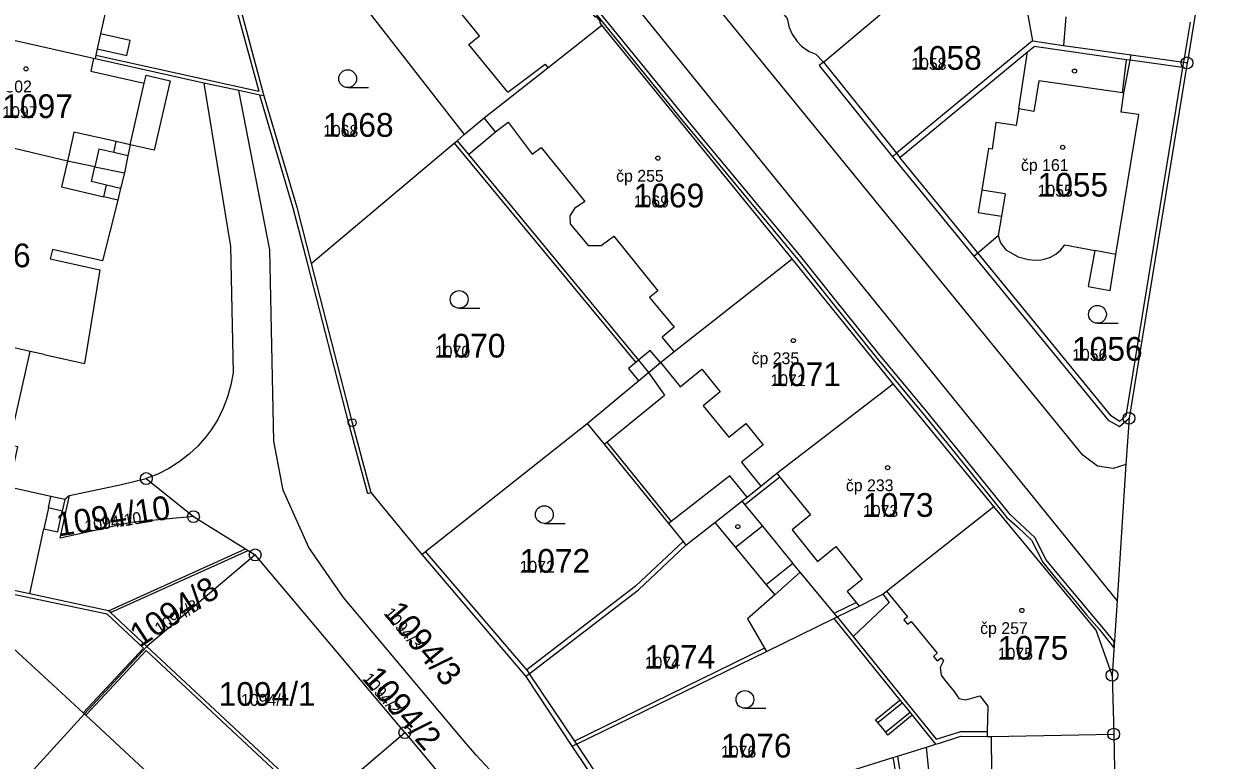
# Model space of a CAD drawing. Extents: x -763628 to -761565, y -976033 to -973833.
# Drawn here: x -761937.4 to -761836.8, y -975033.9 to -974971.8 of the extents above; entities that cross this region are included whole.
import ezdxf

# ---------------------------------------------------------------- set-up
doc = ezdxf.new("R2010")
doc.units = 0
for name, color, linetype in [('KN_cisla parcel 1000', 7, 'Continuous'), ('KN_cisla parcel 500', 7, 'Continuous'), ('KN_cisla popisna 500', 7, 'Continuous'), ('KN_hranice parcel', 7, 'Continuous'), ('KN_hranice uzemi', 7, 'Continuous'), ('KN_vecna bremena', 7, 'Continuous'), ('KN_vnitrni kresba parcel', 7, 'Continuous'), ('KN_znacky bodu BP', 7, 'Continuous'), ('KN_znacky budov', 7, 'Continuous'), ('KN_znacky kultur', 7, 'Continuous')]:
    doc.layers.add(name, color=color, linetype=linetype)

msp = doc.modelspace()

# ---------------------------------------------------------------- linework, layer by layer
at = {"layer": 'KN_hranice parcel'}
for p, q in [((-761919.62, -974968.69), (-761917.15, -974977.91)), ((-761931.5, -974974.74), (-761942.71, -974972.23)), ((-761872.6, -974991.65), (-761888.65, -974971.93)), ((-761919.25, -974977.45), (-761922.2, -974976.82)), ((-761913.16, -974992.03), (-761901.09, -974981.88)), ((-761864.16, -974983.03), (-761857.29, -974991.41)), ((-761864.1, -975002.17), (-761872.6, -974991.65)), ((-761889.88, -975005.51), (-761885.57, -975001.92)), ((-761855.6, -975012.52), (-761864.1, -975002.17)), ((-761927.06, -975010.16), (-761923.08, -975013.37)), ((-761923.08, -975013.37), (-761918.69, -975016.1)), ((-761881.56, -975015.78), (-761879.13, -975013.87)), ((-761930.24, -975021.3), (-761918.69, -975016.1)), ((-761917.88, -975016.6), (-761927.01, -975024.32)), ((-761905.26, -975031.58), (-761917.88, -975016.6)), ((-761903.82, -975016.56), (-761895.06, -975026.86)), ((-761874.78, -975024.73), (-761869.1, -975021.97)), ((-761912.56, -975037.76), (-761927.01, -975024.32)), ((-761895.06, -975026.86), (-761891.17, -975032.73)), ((-761912.56, -975037.76), (-761905.26, -975031.58)), ((-761891.17, -975032.73), (-761885.94, -975040.54))]:
    msp.add_line(p, q, dxfattribs=at)
for points in [[(-761888.65, -974971.93), (-761888.83, -974971.7), (-761888.76, -974971.64), (-761889.1, -974971.2), (-761889.19, -974971.27), (-761891.14, -974968.87), (-761891.06, -974968.8), (-761891.43, -974968.34), (-761891.52, -974968.41), (-761895.5, -974963.62), (-761895.48, -974963.45), (-761896.76, -974961.93), (-761896.92, -974961.89), (-761900.8, -974957.02), (-761900.71, -974956.95), (-761901.09, -974956.5), (-761901.17, -974956.57), (-761903.06, -974954.24), (-761902.95, -974954.15), (-761903.54, -974953.43), (-761903.65, -974953.52)], [(-761869.97, -974975.05), (-761862.24, -974968.54), (-761861.32, -974969.63), (-761857.11, -974965.94), (-761857.81, -974962.69), (-761865.17, -974953.41)], [(-761854.76, -974956.98), (-761853.89, -974963.11), (-761852.83, -974970.61), (-761852.36, -974973.26)], [(-761912.32, -974960.44), (-761909.57, -974964.01), (-761906.72, -974967.16), (-761909, -974969.94), (-761900.25, -974981.17)], [(-761879.04, -974964.81), (-761876.91, -974967.42), (-761876.54, -974967.14), (-761873.03, -974971.39), (-761872.86, -974972.14), (-761872.6, -974972.7), (-761872.19, -974973.32), (-761871.82, -974973.72), (-761871.17, -974974.16), (-761870.6, -974974.39), (-761869.97, -974975.05)], [(-761900.25, -974981.17), (-761898.57, -974979.76), (-761893.21, -974975.53), (-761888.65, -974971.93)], [(-761852.36, -974973.26), (-761863.81, -974982.74), (-761864.16, -974983.03)], [(-761852.36, -974973.26), (-761849.72, -974973.64), (-761844.04, -974974.45)], [(-761849.62, -974990.47), (-761847.1, -974990.94), (-761847.66, -974993.96), (-761845.81, -974994.32), (-761845.31, -974991.27), (-761843.39, -974979.48), (-761844.88, -974979.26), (-761844.64, -974977.66), (-761844.12, -974974.89), (-761844.04, -974974.45)], [(-761844.04, -974974.45), (-761839.62, -974975.07), (-761839.32, -974975.12)], [(-761931.5, -974974.74), (-761931.74, -974975.83), (-761927.23, -974976.84), (-761927.08, -974976.15), (-761925.06, -974976.63), (-761926.4, -974982.48), (-761928.41, -974982.03), (-761928.62, -974982.95), (-761929.8, -974982.68), (-761931.06, -974982.4), (-761931.39, -974983.88), (-761933.7, -974983.4), (-761944.59, -974980.81)], [(-761922.2, -974976.82), (-761931.38, -974974.77), (-761931.5, -974974.74)], [(-761869.97, -974975.05), (-761870.32, -974975.33), (-761864.16, -974983.03)], [(-761922.2, -974976.82), (-761919.95, -974990.59), (-761919.74, -975001.24)], [(-761883.72, -975050.21), (-761899.23, -975033.52), (-761900.44, -975032.09), (-761910.42, -975020.2), (-761913.35, -975015.98), (-761915.51, -975011.15), (-761916.32, -975007), (-761916.64, -974990.89), (-761919.25, -974977.45)], [(-761917.15, -974977.91), (-761917.49, -974977.83), (-761919.25, -974977.45)], [(-761917.15, -974977.91), (-761914.38, -974987.28), (-761913.16, -974992.03)], [(-761901.09, -974981.88), (-761900.86, -974981.69), (-761900.25, -974981.17)], [(-761901.09, -974981.88), (-761885.79, -975000.37), (-761886.42, -975000.89), (-761885.57, -975001.92)], [(-761857.29, -974991.41), (-761856.95, -974991.13), (-761855.23, -974989.67), (-761855.03, -974990.28), (-761854.6, -974990.88), (-761853.56, -974991.46), (-761852.69, -974991.69)], [(-761852.69, -974991.69), (-761852.16, -974991.76), (-761851.61, -974991.73), (-761851.35, -974991.68), (-761850.84, -974991.5), (-761850.37, -974991.24), (-761849.96, -974990.89), (-761849.62, -974990.47)], [(-761885.57, -975001.92), (-761884.71, -975001.21), (-761883.72, -975000.39), (-761882.56, -974999.46), (-761872.6, -974991.65)], [(-761857.29, -974991.41), (-761856.35, -974992.56), (-761845.98, -975005.25), (-761845, -975005.76), (-761844.21, -975005.08)], [(-761913.16, -974992.03), (-761909.7, -975005.45), (-761908.12, -975011.34), (-761903.82, -975016.56)], [(-761933.54, -975011.58), (-761933.93, -975011.93), (-761935.1, -975011.67), (-761938.63, -975010.89), (-761937.88, -975007.5), (-761938.61, -975007.34), (-761936.86, -974999.44), (-761948.14, -974996.86)], [(-761919.74, -975001.24), (-761919.92, -975002.27), (-761920.2, -975003.27), (-761920.58, -975004.24), (-761921.04, -975005.18), (-761921.6, -975006.06), (-761922.01, -975006.61), (-761922.69, -975007.4), (-761923.45, -975008.11), (-761924.28, -975008.75), (-761925.16, -975009.31), (-761926.09, -975009.78), (-761927.06, -975010.16)], [(-761879.13, -975013.87), (-761876.86, -975012.08), (-761876.41, -975011.73), (-761875.24, -975010.81), (-761873.89, -975009.72), (-761864.1, -975002.17)], [(-761903.82, -975016.56), (-761903.51, -975016.31), (-761889.88, -975005.51)], [(-761889.88, -975005.51), (-761888.45, -975007.27), (-761883.04, -975013.96), (-761881.81, -975015.47), (-761881.56, -975015.78)], [(-761933.54, -975011.58), (-761929.16, -975010.65), (-761927.06, -975010.16)], [(-761923.08, -975013.37), (-761928.37, -975013.86), (-761934.32, -975015.19), (-761933.54, -975011.58)], [(-761869.1, -975021.97), (-761868.82, -975021.83), (-761866.96, -975020.92), (-761865.46, -975020.17), (-761864.96, -975019.92), (-761864.66, -975019.66), (-761855.6, -975012.52)], [(-761845.64, -975026.74), (-761846.97, -975022.94), (-761855.6, -975012.52)], [(-761879.13, -975013.87), (-761877.38, -975015.98), (-761874.79, -975019.11), (-761874.08, -975019.96), (-761876.38, -975021.98), (-761874.93, -975024.47), (-761874.78, -975024.73)], [(-761895.06, -975026.86), (-761894.77, -975026.63), (-761885.57, -975019.55), (-761881.56, -975015.78)], [(-761930.24, -975021.3), (-761936.89, -975019.89), (-761940.12, -975019.2), (-761941.16, -975018.98), (-761952.58, -975016.42)], [(-761918.69, -975016.1), (-761918.48, -975016.23), (-761917.88, -975016.6)], [(-761927.01, -975024.32), (-761930.08, -975021.45), (-761930.24, -975021.3)], [(-761869.1, -975021.97), (-761863.52, -975028.84), (-761863.33, -975029.08), (-761862.67, -975029.89), (-761862.48, -975030.12), (-761860.51, -975032.56)], [(-761927.01, -975024.32), (-761932.26, -975030), (-761940.92, -975039.48)], [(-761891.17, -975032.73), (-761890.8, -975032.55), (-761874.78, -975024.73)], [(-761905.26, -975031.58), (-761902.96, -975034.31), (-761892.13, -975047.92)], [(-761860.51, -975032.56), (-761860.2, -975032.46), (-761858.38, -975031.89), (-761856.17, -975031.91), (-761855.84, -975031.91), (-761845.5, -975031.71)], [(-761864.11, -975033.69), (-761863.73, -975033.57), (-761861.29, -975032.8), (-761860.51, -975032.56)], [(-761885.94, -975040.54), (-761885.53, -975040.41), (-761864.11, -975033.69)], [(-761864.11, -975033.69), (-761864.05, -975034.09), (-761863.85, -975035.44), (-761862.06, -975047.4)]]:
    msp.add_lwpolyline(points, dxfattribs=at)
at = {"layer": 'KN_hranice uzemi'}
for p, q in [((-761839.32, -974975.12), (-761844.21, -975005.08)), ((-761845.64, -975026.74), (-761845.5, -975031.71)), ((-761845.5, -975031.71), (-761845.23, -975045.22))]:
    msp.add_line(p, q, dxfattribs=at)
for points in [[(-761836.78, -974959.74), (-761838.75, -974971.73), (-761839.29, -974975.03), (-761839.32, -974975.12)], [(-761844.21, -975005.08), (-761844.47, -975008.99), (-761845.22, -975020.43), (-761845.64, -975026.74)]]:
    msp.add_lwpolyline(points, dxfattribs=at)
at = {"layer": 'KN_vecna bremena'}
for points in [[(-761890.04, -974969.93), (-761881.82, -974980.04), (-761880.23, -974981.93), (-761872.16, -974991.67), (-761869.28, -974995.26), (-761865.58, -974999.87), (-761861.43, -975004.88), (-761858.76, -975008.16), (-761854.5, -975013.44), (-761853.62, -975014.24), (-761852.42, -975015.35), (-761851.48, -975017.2), (-761850.56, -975018.35), (-761848.93, -975020.27), (-761847.78, -975021.65), (-761846.72, -975022.87), (-761845.49, -975024.43), (-761845.45, -975023.91), (-761846.46, -975022.65), (-761847.52, -975021.43), (-761848.67, -975020.05), (-761850.28, -975018.13), (-761851.18, -975017), (-761852.14, -975015.13), (-761853.38, -975013.98)], [(-761853.38, -975013.98), (-761854.24, -975013.2), (-761858.48, -975007.94), (-761861.15, -975004.66), (-761865.3, -974999.65), (-761869, -974995.04), (-761871.88, -974991.45), (-761879.97, -974981.71), (-761881.54, -974979.82), (-761889.76, -974969.71)]]:
    msp.add_lwpolyline(points, dxfattribs=at)
at = {"layer": 'KN_vnitrni kresba parcel'}
for p, q in [((-761848.11, -975008.2), (-761927.52, -974910.73)), ((-761845.22, -975020.43), (-761927.29, -974919.04)), ((-761929.54, -974966.47), (-761930.92, -974972.68)), ((-761920.01, -974968.6), (-761917.58, -974977.51)), ((-761898.96, -974972.84), (-761901.31, -974969.96)), ((-761849.53, -974971.24), (-761849.72, -974973.64)), ((-761839.04, -974971.68), (-761839.62, -974975.07)), ((-761930.92, -974972.68), (-761931.2, -974973.94)), ((-761928.43, -974973.23), (-761930.92, -974972.68)), ((-761928.71, -974974.49), (-761928.43, -974973.23)), ((-761899.86, -974973.57), (-761898.96, -974972.84)), ((-761896.58, -974977.59), (-761899.86, -974973.57)), ((-761931.31, -974974.46), (-761931.38, -974974.77)), ((-761931.2, -974973.94), (-761931.31, -974974.46)), ((-761931.31, -974974.46), (-761917.58, -974977.51)), ((-761931.2, -974973.94), (-761928.71, -974974.49)), ((-761863.52, -974983.09), (-761852.78, -974974.2)), ((-761853.49, -974979), (-761852.78, -974974.2)), ((-761852.78, -974974.2), (-761852.21, -974973.73)), ((-761844.43, -974974.85), (-761852.21, -974973.73)), ((-761896.58, -974977.59), (-761893.44, -974975.24)), ((-761893.44, -974975.24), (-761893.21, -974975.53)), ((-761869.97, -974975.05), (-761863.81, -974982.74)), ((-761844.76, -974977.64), (-761844.43, -974974.85)), ((-761839.69, -974975.52), (-761844.48, -975004.88)), ((-761844.12, -974974.89), (-761844.43, -974974.85)), ((-761839.69, -974975.52), (-761844.12, -974974.89)), ((-761839.62, -974975.07), (-761839.69, -974975.52)), ((-761851.8, -974976.62), (-761852.23, -974979.21)), ((-761844.76, -974977.64), (-761851.8, -974976.62)), ((-761928.41, -974982.03), (-761927.23, -974976.84)), ((-761844.64, -974977.66), (-761844.76, -974977.64)), ((-761914.67, -974987.37), (-761917.49, -974977.83)), ((-761853.49, -974979), (-761853.72, -974980.41)), ((-761852.23, -974979.21), (-761853.49, -974979)), ((-761897.63, -974980.93), (-761898.57, -974979.76)), ((-761897.63, -974980.93), (-761896.55, -974980.12)), ((-761896.55, -974980.12), (-761894.52, -974982.81)), ((-761855.43, -974980.15), (-761855.76, -974982.38)), ((-761853.72, -974980.41), (-761855.43, -974980.15)), ((-761933.25, -974981.38), (-761933.7, -974983.4)), ((-761933.16, -974980.96), (-761933.25, -974981.38)), ((-761929.59, -974981.76), (-761933.16, -974980.96)), ((-761899.9, -974982.83), (-761897.63, -974980.93)), ((-761929.8, -974982.68), (-761929.59, -974981.76)), ((-761928.41, -974982.03), (-761929.59, -974981.76)), ((-761900.86, -974981.69), (-761899.9, -974982.83)), ((-761894.52, -974982.81), (-761893.77, -974982.24)), ((-761893.77, -974982.24), (-761890.1, -974986.8)), ((-761856.05, -974982.34), (-761856.62, -974985.84)), ((-761855.76, -974982.38), (-761856.05, -974982.34)), ((-761933.7, -974983.4), (-761934.22, -974985.58)), ((-761928.62, -974982.95), (-761928.9, -974984.39)), ((-761899.9, -974982.83), (-761885.56, -975000.18)), ((-761863.81, -974982.74), (-761863.52, -974983.09)), ((-761856.95, -974991.13), (-761863.52, -974983.09)), ((-761931.67, -974985.13), (-761931.39, -974983.88)), ((-761931.39, -974983.88), (-761928.9, -974984.39)), ((-761928.9, -974984.39), (-761929.23, -974985.7)), ((-761934.22, -974985.58), (-761930.64, -974986.42)), ((-761930.41, -974985.42), (-761931.67, -974985.13)), ((-761930.64, -974986.42), (-761930.41, -974985.42)), ((-761929.23, -974985.7), (-761930.41, -974985.42)), ((-761929.47, -974986.69), (-761930.74, -974991.8)), ((-761929.47, -974986.69), (-761930.64, -974986.42)), ((-761929.23, -974985.7), (-761929.47, -974986.69)), ((-761856.62, -974985.84), (-761856.93, -974987.73)), ((-761854.66, -974986.16), (-761856.62, -974985.84)), ((-761854.66, -974986.16), (-761854.97, -974988.05)), ((-761913.45, -974992.1), (-761914.67, -974987.37)), ((-761890.96, -974987.39), (-761891.35, -974988.01)), ((-761890.1, -974986.8), (-761890.96, -974987.39)), ((-761891.35, -974988.01), (-761891.32, -974988.7)), ((-761891.32, -974988.7), (-761889.82, -974990.52)), ((-761856.93, -974987.73), (-761854.97, -974988.05)), ((-761854.97, -974988.05), (-761855.23, -974989.67)), ((-761889.82, -974990.52), (-761888.71, -974990.51)), ((-761888.71, -974990.51), (-761887.63, -974989.72)), ((-761887.63, -974989.72), (-761883.93, -974994.33)), ((-761934.97, -974990.84), (-761935.16, -974991.64)), ((-761935.16, -974991.64), (-761930.97, -974992.56)), ((-761930.74, -974991.8), (-761934.97, -974990.84)), ((-761845.71, -975004.88), (-761856.95, -974991.13)), ((-761845.31, -974991.27), (-761847.1, -974990.94)), ((-761930.97, -974992.56), (-761932.26, -975000.45)), ((-761909.99, -975005.52), (-761913.45, -974992.1)), ((-761883.93, -974994.33), (-761884.63, -974994.89)), ((-761884.63, -974994.89), (-761882.57, -974997.41)), ((-761882.57, -974997.41), (-761883.57, -974998.25)), ((-761882.56, -974999.46), (-761883.57, -974998.25)), ((-761935.68, -974999.7), (-761936.86, -974999.44)), ((-761935.68, -974999.7), (-761932.26, -975000.45)), ((-761884.58, -974999.36), (-761885.56, -975000.18)), ((-761883.72, -975000.39), (-761884.58, -974999.36)), ((-761885.56, -975000.18), (-761885.79, -975000.37)), ((-761885.56, -975000.18), (-761884.71, -975001.21)), ((-761883.72, -975000.39), (-761882.22, -975002.2)), ((-761884.71, -975001.21), (-761883.38, -975003.14)), ((-761882.04, -975002.43), (-761880.22, -975000.95)), ((-761880.22, -975000.95), (-761878.67, -975002.86)), ((-761882.22, -975002.2), (-761882.04, -975002.43)), ((-761888.22, -975007.08), (-761883.38, -975003.14)), ((-761878.67, -975002.86), (-761880.1, -975004.02)), ((-761880.1, -975004.02), (-761877.95, -975006.68)), ((-761908.39, -975011.46), (-761909.99, -975005.52)), ((-761877.95, -975006.68), (-761876.51, -975005.52)), ((-761876.51, -975005.52), (-761875.06, -975007.31)), ((-761845.02, -975005.34), (-761845.71, -975004.88)), ((-761844.48, -975004.88), (-761845.02, -975005.34)), ((-761888.45, -975007.27), (-761888.22, -975007.08)), ((-761888.22, -975007.08), (-761882.8, -975013.78)), ((-761875.06, -975007.31), (-761876.88, -975008.79)), ((-761876.88, -975008.79), (-761876.69, -975009.03)), ((-761846.86, -975009.12), (-761848.11, -975008.2)), ((-761876.69, -975009.03), (-761875.24, -975010.81)), ((-761873.89, -975009.72), (-761873.64, -975010.04)), ((-761845.54, -975009.31), (-761846.86, -975009.12)), ((-761844.47, -975008.99), (-761845.54, -975009.31)), ((-761877.87, -975009.94), (-761882.8, -975013.78)), ((-761876.41, -975011.73), (-761877.87, -975009.94)), ((-761873.64, -975010.04), (-761876.6, -975012.39)), ((-761873.64, -975010.04), (-761871.07, -975013.23)), ((-761935.31, -975012.64), (-761935.1, -975011.67)), ((-761908.12, -975011.34), (-761908.39, -975011.46)), ((-761935.31, -975012.64), (-761935.69, -975014.39)), ((-761934.14, -975012.9), (-761935.31, -975012.64)), ((-761933.93, -975011.93), (-761934.14, -975012.9)), ((-761876.86, -975012.08), (-761876.6, -975012.39)), ((-761876.6, -975012.39), (-761875.12, -975014.18)), ((-761934.53, -975014.65), (-761934.14, -975012.9)), ((-761882.8, -975013.78), (-761883.04, -975013.96)), ((-761871.07, -975013.23), (-761872.62, -975014.48)), ((-761936.89, -975019.89), (-761935.69, -975014.39)), ((-761935.69, -975014.39), (-761934.53, -975014.65)), ((-761875.12, -975014.18), (-761877.38, -975015.98)), ((-761875.12, -975014.18), (-761872.55, -975017.31)), ((-761872.62, -975014.48), (-761870.47, -975017.14)), ((-761881.81, -975015.47), (-761885.81, -975019.23)), ((-761930.08, -975021.45), (-761918.48, -975016.23)), ((-761894.99, -975026.3), (-761903.51, -975016.31)), ((-761870.47, -975017.14), (-761868.93, -975015.9)), ((-761868.93, -975015.9), (-761866.7, -975018.67)), ((-761872.55, -975017.31), (-761874.79, -975019.11)), ((-761871.93, -975018.06), (-761872.55, -975017.31)), ((-761874.08, -975019.96), (-761871.93, -975018.06)), ((-761869.08, -975021.51), (-761871.93, -975018.06)), ((-761866.7, -975018.67), (-761867.96, -975019.68)), ((-761930.36, -975021.58), (-761939.99, -975019.57)), ((-761885.81, -975019.23), (-761894.99, -975026.3)), ((-761867.96, -975019.68), (-761867.22, -975020.6)), ((-761864.66, -975019.66), (-761862.88, -975021.83)), ((-761869.08, -975021.51), (-761867.22, -975020.6)), ((-761867.47, -975023.49), (-761864.42, -975020.61)), ((-761867.22, -975020.6), (-761866.96, -975020.92)), ((-761864.96, -975019.92), (-761864.42, -975020.61)), ((-761927.3, -975024.46), (-761930.36, -975021.58)), ((-761868.82, -975021.83), (-761869.08, -975021.51)), ((-761868.82, -975021.83), (-761867.47, -975023.49)), ((-761862.88, -975021.83), (-761863.19, -975022.08)), ((-761863.19, -975022.08), (-761862.88, -975022.45)), ((-761862.88, -975022.45), (-761862.58, -975022.2)), ((-761862.58, -975022.2), (-761860.37, -975024.89)), ((-761867.47, -975023.49), (-761860.47, -975032.13)), ((-761938.59, -975024.19), (-761932.37, -975029.9)), ((-761927.3, -975024.46), (-761932.37, -975029.9)), ((-761927.08, -975024.66), (-761932.15, -975030.1)), ((-761912.88, -975037.88), (-761927.08, -975024.66)), ((-761874.93, -975024.47), (-761890.97, -975032.3)), ((-761860.37, -975024.89), (-761860.68, -975025.15)), ((-761860.68, -975025.15), (-761860.37, -975025.53)), ((-761860.37, -975025.53), (-761860.06, -975025.28)), ((-761859.84, -975025.54), (-761860.13, -975026.08)), ((-761860.06, -975025.28), (-761859.84, -975025.54)), ((-761894.99, -975026.3), (-761894.77, -975026.63)), ((-761894.77, -975026.63), (-761890.97, -975032.3)), ((-761860.13, -975026.08), (-761860.05, -975026.75)), ((-761860.05, -975026.75), (-761859.75, -975027.15)), ((-761859.75, -975027.15), (-761858.96, -975028.12)), ((-761865.57, -975030.51), (-761863.52, -975028.84)), ((-761858.96, -975028.12), (-761858.56, -975028.69)), ((-761858.56, -975028.69), (-761857.98, -975028.81)), ((-761857.98, -975028.81), (-761856.79, -975028.49)), ((-761856.79, -975028.49), (-761856.11, -975029.36)), ((-761932.26, -975030), (-761932.37, -975029.9)), ((-761865.38, -975030.74), (-761863.33, -975029.08)), ((-761862.67, -975029.89), (-761864.72, -975031.55)), ((-761856.11, -975029.36), (-761856.16, -975031.52)), ((-761932.26, -975030), (-761932.15, -975030.1)), ((-761932.15, -975030.1), (-761917.97, -975043.29)), ((-761865.38, -975030.74), (-761865.57, -975030.51)), ((-761864.72, -975031.55), (-761865.38, -975030.74)), ((-761862.48, -975030.12), (-761864.53, -975031.79)), ((-761864.53, -975031.79), (-761864.72, -975031.55)), ((-761860.47, -975032.13), (-761858.47, -975031.5)), ((-761856.16, -975031.52), (-761858.47, -975031.5)), ((-761856.16, -975031.52), (-761856.17, -975031.91)), ((-761855.84, -975031.91), (-761855.79, -975034.92)), ((-761890.97, -975032.3), (-761890.8, -975032.55)), ((-761890.8, -975032.55), (-761885.53, -975040.41)), ((-761861.06, -975035.02), (-761861.29, -975032.8)), ((-761863.73, -975033.57), (-761863.46, -975035.38))]:
    msp.add_line(p, q, dxfattribs=at)
at = {"layer": 'KN_znacky bodu BP'}
for centre, radius in [((-761839.32, -974975.12), 0.5), ((-761839.32, -974975.12), 0.0303), ((-761844.21, -975005.08), 0.5), ((-761909.7, -975005.45), 0.335), ((-761909.7, -975005.45), 0.0203), ((-761844.21, -975005.08), 0.0303), ((-761927.06, -975010.16), 0.5), ((-761927.06, -975010.16), 0.0303), ((-761923.08, -975013.37), 0.5), ((-761923.08, -975013.37), 0.0303), ((-761917.88, -975016.6), 0.5), ((-761917.88, -975016.6), 0.0303), ((-761845.64, -975026.74), 0.5), ((-761845.64, -975026.74), 0.0303), ((-761905.26, -975031.58), 0.5), ((-761905.26, -975031.58), 0.0303), ((-761845.5, -975031.71), 0.5), ((-761845.5, -975031.71), 0.0303)]:
    msp.add_circle(centre, radius, dxfattribs=at)
at = {"layer": 'KN_znacky budov'}
for centre in [(-761937.2, -974975.62), (-761848.8, -974975.81), (-761849.8, -974982.24), (-761883.93, -974983.15), (-761872.51, -974998.53), (-761864.56, -975009.24), (-761877.19, -975014.21), (-761853.24, -975021.28)]:
    msp.add_circle(centre, 0.175, dxfattribs=at)
at = {"layer": 'KN_znacky kultur'}
for p, q in [((-761910.08, -974977.2), (-761908.33, -974977.2)), ((-761900.68, -974995.81), (-761898.93, -974995.81)), ((-761846.87, -974997.07), (-761845.12, -974997.07)), ((-761893.5, -975013.95), (-761891.75, -975013.95)), ((-761876.59, -975029.53), (-761874.84, -975029.53))]:
    msp.add_line(p, q, dxfattribs=at)
for centre in [(-761910.08, -974976.45), (-761900.68, -974995.06), (-761846.87, -974996.32), (-761893.5, -975013.2), (-761876.59, -975028.78)]:
    msp.add_circle(centre, 0.75, dxfattribs=at)

# ---------------------------------------------------------------- texts
at = {"layer": 'KN_cisla parcel 1000'}
for s, p in [('1058', (-761862.57, -974975.7)), ('1097', (-761939.2, -974979.77)), ('1068', (-761912.16, -974981.35)), ('1055', (-761851.92, -974986.39)), ('1069', (-761885.97, -974987.3)), ('1096', (-761942.76, -974992.35)), ('1070', (-761902.73, -974999.96)), ('1056', (-761849.01, -975000.23)), ('1071', (-761874.44, -975002.37)), ('1073', (-761866.64, -975013.39)), ('1072', (-761895.59, -975018.1)), ('1075', (-761855.28, -975025.43)), ('1074', (-761885.04, -975026.19)), ('1094/1', (-761920.96, -975029.32)), ('1076', (-761878.61, -975033.68))]:
    msp.add_text(s, height=2, dxfattribs=at).set_placement(p)
for s, rotation, p in [('1094/10', 9, (-761934.47, -975015.05)), ('1094/8', 33, (-761927.6, -975024.43)), ('1094/3', 310, (-761907.1, -975021.55)), ('1094/2', 311, (-761908.91, -975027.07))]:
    msp.add_text(s, height=2, rotation=rotation, dxfattribs=at).set_placement(p)
at = {"layer": 'KN_cisla parcel 500'}
for s, p in [('1058', (-761862.57, -974975.7)), ('1097', (-761939.2, -974979.77)), ('1068', (-761912.16, -974981.35)), ('1055', (-761851.92, -974986.39)), ('1069', (-761885.97, -974987.3)), ('1070', (-761902.73, -974999.96)), ('1056', (-761849.01, -975000.23)), ('1071', (-761874.44, -975002.37)), ('1073', (-761866.64, -975013.39)), ('1072', (-761895.59, -975018.1)), ('1075', (-761855.28, -975025.43)), ('1074', (-761885.04, -975026.19)), ('1094/1', (-761919.08, -975029.32)), ('1076', (-761878.61, -975033.68))]:
    msp.add_text(s, height=1, dxfattribs=at).set_placement(p)
for s, rotation, p in [('1094/10', 9, (-761932.18, -975014.69)), ('1094/8', 33, (-761925.94, -975023.35)), ('1094/3', 310, (-761907.1, -975021.55)), ('1094/2', 311, (-761908.91, -975027.07))]:
    msp.add_text(s, height=1, rotation=rotation, dxfattribs=at).set_placement(p)
at = {"layer": 'KN_cisla popisna 500'}
for s, p in [('čp 802', (-761940.72, -974977.61)), ('čp 161', (-761853.32, -974984.23)), ('čp 255', (-761887.45, -974985.14)), ('čp 235', (-761876.03, -975000.52)), ('čp 233', (-761868.08, -975011.23)), ('čp 257', (-761856.76, -975023.27))]:
    msp.add_text(s, height=1, dxfattribs=at).set_placement(p)

doc.saveas('drawing.dxf')
